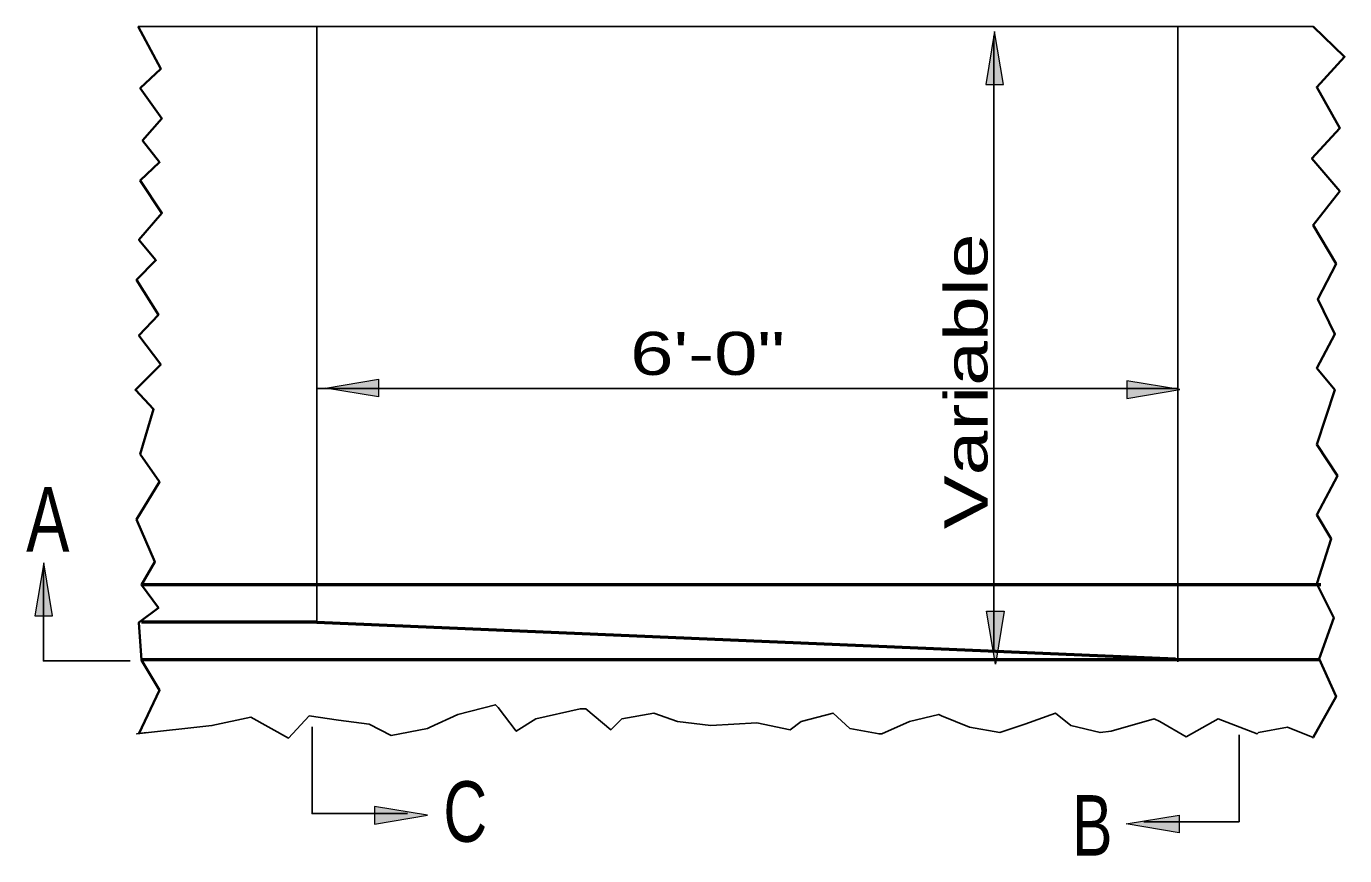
# Model space of a CAD drawing. Extents: x 75.6 to 110.9, y 28 to 50.
# Drawn here: x 93.441 to 98.035, y 42.217 to 45.106 of the extents above; entities that cross this region are included whole.
import ezdxf
from ezdxf.enums import TextEntityAlignment as Align

# ---------------------------------------------------------------- set-up
doc = ezdxf.new("R2010")
doc.units = 0
doc.header["$LTSCALE"] = 0.06
doc.layers.add('1', color=7, linetype='Continuous', lineweight=25)
doc.layers.add('3', color=7, linetype='Continuous', lineweight=13)

msp = doc.modelspace()

# ---------------------------------------------------------------- hatches: boundary and pattern name
at = {"layer": '3'}
for points in [[(96.78417, 44.90417), (96.84567, 44.90417), (96.81492, 45.08875), (96.81492, 45.08875)], [(94.6675, 43.87658), (94.6675, 43.81508), (94.48292, 43.84592), (94.48292, 43.84592)], [(97.27608, 43.87117), (97.27608, 43.80967), (97.46075, 43.8405), (97.46075, 43.8405)], [(93.47083, 43.052), (93.53233, 43.052), (93.50158, 43.23658), (93.50158, 43.23658)], [(96.78683, 43.06825), (96.84833, 43.06825), (96.81758, 42.88367), (96.81758, 42.88367)], [(94.65425, 42.388), (94.65425, 42.3265), (94.83892, 42.35733), (94.83892, 42.35733)], [(97.45817, 42.35758), (97.45817, 42.29608), (97.27358, 42.32692), (97.27358, 42.32692)]]:
    msp.add_hatch(color=256, dxfattribs=at).paths.add_polyline_path(points)

# ---------------------------------------------------------------- linework, layer by layer
at = {"layer": '1'}
for p, q in [((97.92483, 45.10633), (93.831, 45.10633)), ((94.45342, 45.10633), (94.45342, 43.03)), ((96.81225, 45.07258), (96.81225, 42.92925)), ((97.45358, 45.10633), (97.45358, 42.89233)), ((97.45042, 43.84475), (94.45025, 43.84475))]:
    msp.add_line(p, q, dxfattribs=at)
at = {"layer": '1', "lineweight": 53}
for p, q in [((97.95167, 43.16075), (93.84183, 43.16075)), ((94.45342, 43.03), (93.84192, 43.03)), ((94.45342, 43.03), (97.44525, 42.90233)), ((97.94592, 42.89917), (93.83992, 42.89917))]:
    msp.add_line(p, q, dxfattribs=at)
at = {"layer": '1', "lineweight": 35}
for points in [[(93.831, 45.10633), (93.90933, 44.95808), (93.83758, 44.89058), (93.91358, 44.785), (93.846, 44.709), (93.90517, 44.633), (93.83758, 44.56975), (93.91358, 44.45575), (93.83342, 44.36292), (93.89242, 44.29117), (93.82492, 44.22358), (93.90092, 44.10117), (93.83342, 44.02933), (93.90933, 43.92808), (93.82075, 43.83942), (93.884, 43.77192), (93.83758, 43.61567), (93.90517, 43.51858), (93.82492, 43.38775), (93.88825, 43.24), (93.84183, 43.15975), (93.90092, 43.07958), (93.83342, 43.029), (93.84183, 42.898), (93.90517, 42.79258), (93.83342, 42.64058)], [(97.92483, 45.10633), (98.03458, 45.00033), (97.9375, 44.89475), (98.01767, 44.75125), (97.92058, 44.64575), (98.01767, 44.53175), (97.92483, 44.41358), (98.005, 44.27842), (97.94175, 44.156), (98.00083, 44.03358), (97.9375, 43.91533), (98.00083, 43.83942), (97.9375, 43.6495), (98.00925, 43.53967), (97.9375, 43.40467), (97.98817, 43.32017), (97.9375, 43.164), (97.99658, 43.04575), (97.94592, 42.90233), (98.005, 42.77133), (97.92483, 42.62792), (97.92483, 42.62792)]]:
    msp.add_lwpolyline(points, dxfattribs=at)
at = {"layer": '1'}
for points in [[(93.80283, 42.895), (93.50042, 42.895), (93.50042, 43.22758)], [(97.92483, 42.62792), (97.83592, 42.66475), (97.73425, 42.64533), (97.72942, 42.6405), (97.59383, 42.69375), (97.48242, 42.63083), (97.39042, 42.68408), (97.371, 42.69375), (97.22092, 42.65017), (97.18225, 42.64533), (97.0805, 42.66958), (97.02725, 42.71317), (96.92067, 42.67442), (96.83358, 42.64533), (96.727, 42.66475), (96.63017, 42.7035), (96.62042, 42.70833), (96.51875, 42.68408), (96.42192, 42.6405), (96.41225, 42.6405), (96.3105, 42.65992), (96.25242, 42.71317), (96.141, 42.68408), (96.10225, 42.655), (95.986, 42.67933), (95.82625, 42.66958), (95.71, 42.68408), (95.62767, 42.71317), (95.51625, 42.69375), (95.47758, 42.655), (95.39042, 42.72775), (95.371, 42.72775), (95.216, 42.69375), (95.14825, 42.65017), (95.08525, 42.73258), (95.07558, 42.74225), (94.94492, 42.70833), (94.848, 42.66475), (94.83833, 42.65992), (94.71242, 42.63567), (94.63492, 42.67442), (94.52842, 42.689), (94.42667, 42.7035), (94.354, 42.626), (94.22325, 42.69867), (94.08767, 42.66958), (93.82492, 42.64058), (93.86008, 42.64533)], [(94.43633, 42.66575), (94.43633, 42.36333), (94.76892, 42.36333)], [(97.667, 42.63717), (97.667, 42.33483), (97.33433, 42.33483)]]:
    msp.add_lwpolyline(points, dxfattribs=at)
at = {"layer": '3'}
for points in [[(96.78417, 44.90417), (96.84567, 44.90417), (96.81492, 45.08875), (96.81492, 45.08875)], [(94.6675, 43.87658), (94.6675, 43.81508), (94.48292, 43.84592), (94.48292, 43.84592)], [(97.27608, 43.87117), (97.27608, 43.80967), (97.46075, 43.8405), (97.46075, 43.8405)], [(93.47083, 43.052), (93.53233, 43.052), (93.50158, 43.23658), (93.50158, 43.23658)], [(96.78683, 43.06825), (96.84833, 43.06825), (96.81758, 42.88367), (96.81758, 42.88367)], [(94.65425, 42.388), (94.65425, 42.3265), (94.83892, 42.35733), (94.83892, 42.35733)], [(97.45817, 42.35758), (97.45817, 42.29608), (97.27358, 42.32692), (97.27358, 42.32692)]]:
    msp.add_lwpolyline(points, close=True, dxfattribs=at)

# ---------------------------------------------------------------- texts
at = {"layer": '1', "width": 1.4}
msp.add_text('Variable', height=0.15, rotation=90, dxfattribs=at).set_placement((96.79017, 43.86954), align=Align.CENTER)
at = {"layer": '1'}
for s, height, width, p in [('6\'-0"', 0.15, 1.35, (95.81488, 43.89175)), ('A', 0.225, 0.75, (93.51579, 43.276)), ('C', 0.2109, 0.75, (94.97037, 42.26467)), ('B', 0.2109, 0.75, (97.15533, 42.2165))]:
    msp.add_text(s, height=height, dxfattribs=dict(at, width=width)).set_placement(p, align=Align.CENTER)

doc.saveas('drawing.dxf')
